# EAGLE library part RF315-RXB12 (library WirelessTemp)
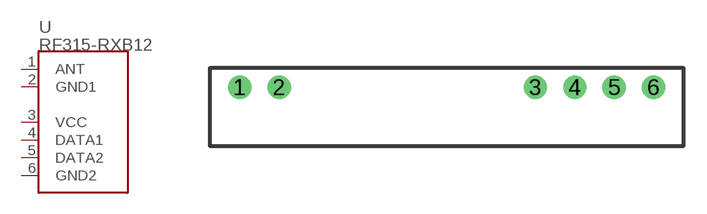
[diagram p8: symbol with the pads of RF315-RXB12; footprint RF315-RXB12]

Designator prefix U

## RF315-RXB12  [RF315-RXB12]
1  ANT  in
2  GND1  pwr
3  VCC  pwr
4  DATA1  out
5  DATA2  out
6  GND2  pwr

## Footprint RF315-RXB12 (pad centres in mm)
drill 1 round: 1 -12.7,0; 2 -10.16,0; 3 6.35,0; 4 8.89,0; 5 11.43,0; 6 13.97,0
